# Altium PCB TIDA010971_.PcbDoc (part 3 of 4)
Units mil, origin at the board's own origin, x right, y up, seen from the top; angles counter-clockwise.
Board outline 4500 x 6000 mil, 2 copper layers (F.CU, B.CU), stack 60.617 mil thick; 280 components, 124 nets, 681 pads, 871 vias.
Unrouted connection lines stored in the file: 1.
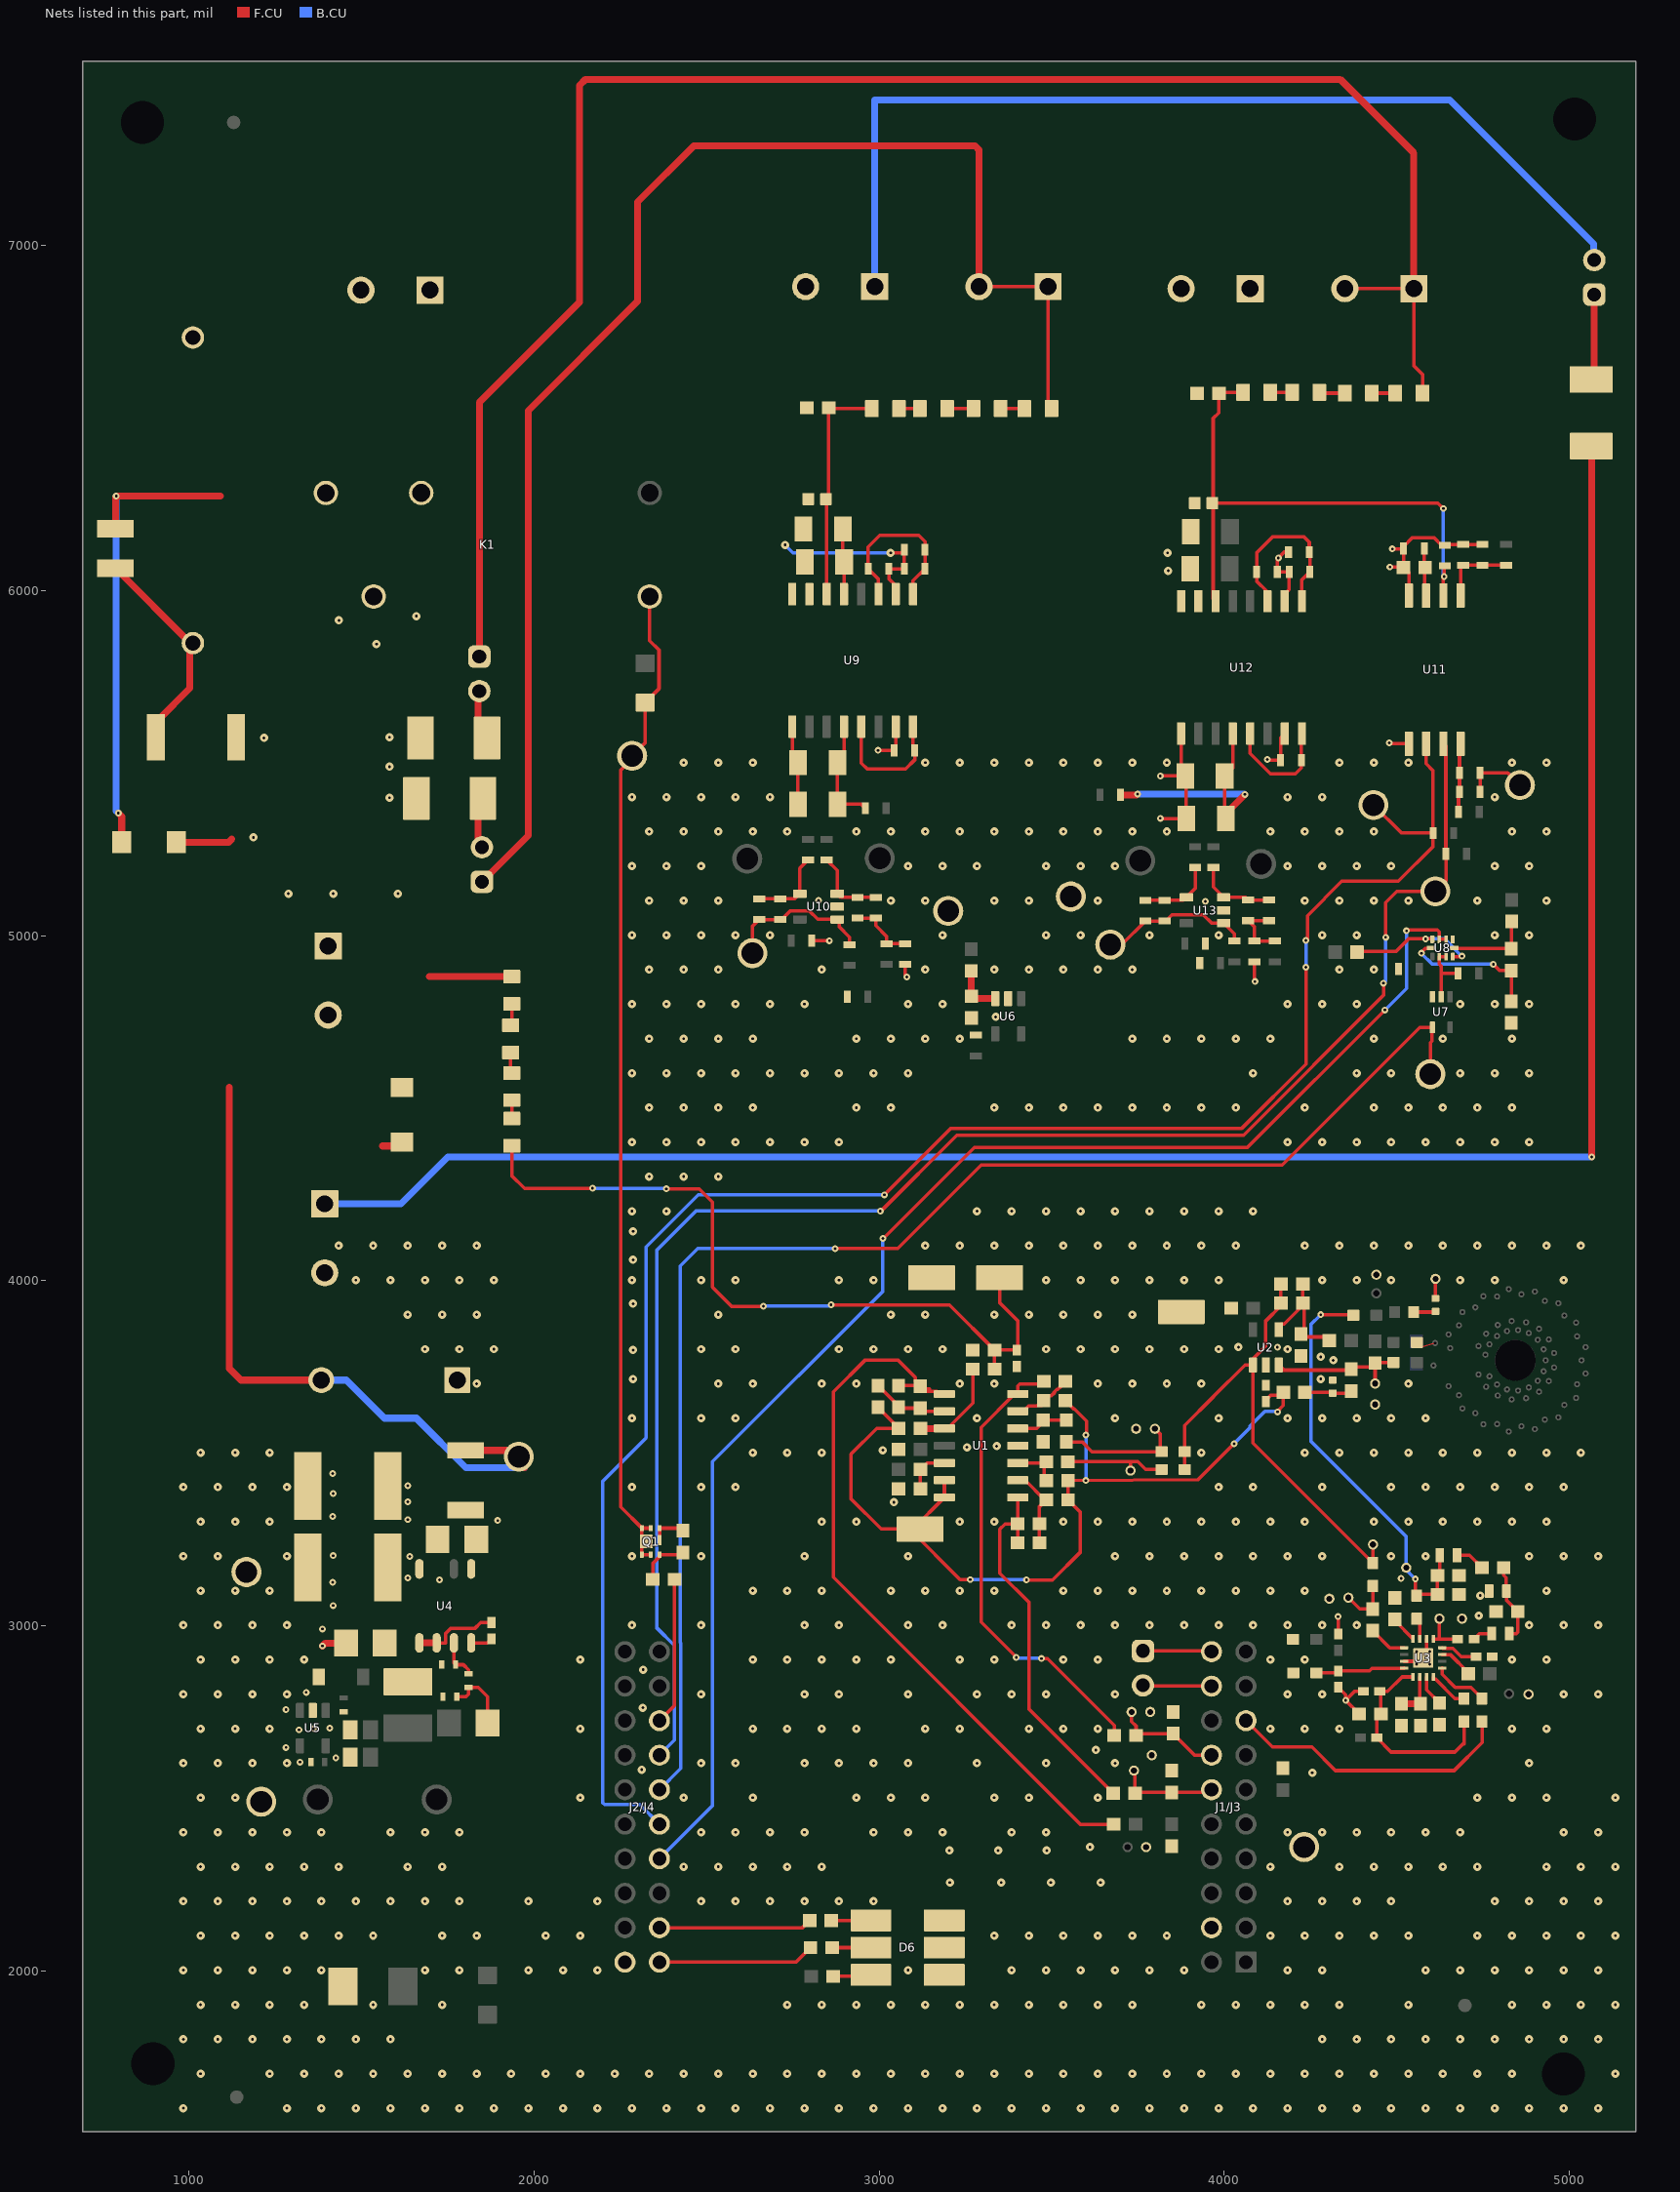
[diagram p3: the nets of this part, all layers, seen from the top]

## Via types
v1: diameter 24, hole 8, F.CU to B.CU, tented both sides, 774 vias
v2: diameter 19.68, hole 7.87, F.CU to B.CU, tented both sides, 97 vias

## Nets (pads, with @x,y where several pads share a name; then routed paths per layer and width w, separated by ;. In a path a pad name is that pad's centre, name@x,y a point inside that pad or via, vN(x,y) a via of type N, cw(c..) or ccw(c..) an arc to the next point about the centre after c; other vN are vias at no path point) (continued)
AGND: AGND2.1 AGND3.1 C2.1 C3.1 C4.1 C5.1 C7.2 C8.1 C9.2 C10.1 C12.2 C13.1 C16.2 C17.2 C18.2 C19.2 C22.2 C23.2 C24.2 C25.2 C26.2 C27.2 C28.2 C31.2 C33.1 C37.2 C39.2 C43.2 C44.2 C45.2 C49.2 C50.2 C54.2 C57.2 C58.2 C64.2 C65.2 C66.1 C67.2 C68.1 C69.1 C72.2 D3.2 D4.2 D6.1 D6.2 D6.3 D7.1 D10.2 F2.2 GND.1 J1/J3.22 J2/J4.20 J9.1 J9.2 L1.1 L4.1 Neutral.1 Q1.4 Q1.7 R15.1 R19.1 R24.2 R25.1 R29.1 R48.2 R65.2 R68.2 R69.1 R76.1 R81.1 R88.1 TP7.1 TP11.1 TP15.1 TP18.1 TP20.1 TP22.1 TP24.1 TP25.1 TP26.1 TP_AGND1.1 TP_AGND2.1 TP_AGND3.1 TP_AGND.1 U1.11 U2.2 U3.10 U3.15 U3.17 U5.2 U6.2 U7.3 U8.1 U9.9 U9.15 U10.2 U11.5 U12.9 U12.15 U13.2 | length 7631.9
  F.CU w10: Q1.7@2363.33,3248.24 Q1.4@2363.33,3282.89 2423.35,3282.89 R76.1@2430.8,3275.44 ; U9.9@2747.75,5605.99 2747.75,5518.41 C43.2@2764.47,5501.68 C44.2@2764.47,5380.95 ; C39.2@2804.43,4985.88 2804.77,4985.54 v2(2855.73,4985.54) ; v2(2996.57,5537.08) C37.2@3042.67,5537.12 3047.75,5542.2 U9.15@3047.75,5605.99 ; R48.2@3075.48,4916.54 3075.48,4887.43 3080.04,4882.87 v2(3080.04,4880.25) ; U1.11@3401.33,3521.86 U1.11@3403.27,3519.93 ; v2(3814.48,5340.25) 3815.23,5339.5 C64.2@3889.75,5339.5 3889.75,5459.99 C65.2@3886.83,5462.92 ; v2(3814.48,5462.92) C65.2@3886.83,5462.92 ; U12.9@3874.85,5585.66 3874.85,5474.9 C65.2@3886.83,5462.92 ; R65.2@4086.74,4928.22 R65.2@4086.74,4924.66 4086.74,4869.07 v2(4088.71,4867.1) ; v2(4124.85,5510.55) 4126.23,5509.18 C58.2@4163.28,5509.18 4163.28,5574.09 U12.15@4174.85,5585.66 ; C66.1@4329.9,2821.73 4351.55,2800.08 v2(4351.55,2783.89) ; C67.2@4329.9,2976.01 v2(4329.92,3026.63) ; C68.1@4390.8,2744.58 4351.55,2783.83 v2(4351.55,2783.89) ; C69.1@4403.37,2809.92 4377.58,2809.92 v2(4351.55,2783.89) ; v2(4477.6,5558.65) 4479.86,5556.39 U11.5@4534.82,5556.39 ; U3.15@4521.12,2896.98 4566.39,2896.98 U3.17@4576.23,2906.83 ; U3.10@4586.08,2961.94 4586.08,2934.38 v2(4594.93,2925.53) ; C49.2@4741.5,5416.66 C50.2@4741.5,5471.77 4821.33,5471.77 TP_AGND3.1@4856.76,5436.34
  F.CU w20: v2(1386.55,2941.54) 1394.89,2949.87 D4.2@1454.51,2949.87 ; 1560.45,4390.45 1605.31,4390.45 D7.1@1616.53,4401.67 ; TP_AGND3.1@4856.76,5436.34 TP_AGND3.1@4871.76,5421.34 ; F2.2@5063.13,6419.21 5065,6417.34 v2(5065,4359)
  B.CU w20: J9.1@1390.97,4223 J9.1@1393,4223 1614,4223 1750,4359 v2(5065,4359)
  other v1: 983.37,1601.73 1283.37,1601.73 1383.37,1601.73 1483.37,1601.73 1583.37,1601.73 1683.37,1601.73 1783.37,1601.73 1883.37,1601.73 1983.37,1601.73 2083.37,1601.73 2183.37,1601.73 2283.37,1601.73 2383.37,1601.73 2483.37,1601.73 2583.37,1601.73 2683.37,1601.73 2783.37,1601.73 2883.37,1601.73 2983.37,1601.73 3083.37,1601.73 3183.37,1601.73 3283.37,1601.73 3383.37,1601.73 3483.37,1601.73 3583.37,1601.73 3683.37,1601.73 3783.37,1601.73 3883.37,1601.73 3983.37,1601.73 4083.37,1601.73 4183.37,1601.73 4283.37,1601.73 4383.37,1601.73 4483.37,1601.73 4583.37,1601.73 4683.37,1601.73 4783.37,1601.73 4883.37,1601.73 4983.37,1601.73 5083.37,1601.73 1033.37,1701.73 1233.37,1701.73 1333.37,1701.73 1433.37,1701.73 1533.37,1701.73 1633.37,1701.73 1733.37,1701.73 1833.37,1701.73 1933.37,1701.73 2033.37,1701.73 2133.37,1701.73 2233.37,1701.73 2333.37,1701.73 2433.37,1701.73 2533.37,1701.73 2633.37,1701.73 2733.37,1701.73 2833.37,1701.73 2933.37,1701.73 3033.37,1701.73 3133.37,1701.73 3233.37,1701.73 3333.37,1701.73 3433.37,1701.73 3533.37,1701.73 3633.37,1701.73 3733.37,1701.73 3833.37,1701.73 3933.37,1701.73 4033.37,1701.73 4133.37,1701.73 4233.37,1701.73 4333.37,1701.73 4433.37,1701.73 4533.37,1701.73 4633.37,1701.73 4733.37,1701.73 4833.37,1701.73 5133.37,1701.73 983.37,1801.73 1083.37,1801.73 1183.37,1801.73 1283.37,1801.73 1383.37,1801.73 1483.37,1801.73 1583.37,1801.73 4283.37,1801.73 4383.37,1801.73 4483.37,1801.73 4583.37,1801.73 4683.37,1801.73 4783.37,1801.73 4883.37,1801.73 4983.37,1801.73 5083.37,1801.73 1033.37,1901.73 1133.37,1901.73 1233.37,1901.73 1333.37,1901.73 1533.37,1901.73 1733.37,1901.73 2733.37,1901.73 2833.37,1901.73 2933.37,1901.73 3033.37,1901.73 3133.37,1901.73 3233.37,1901.73 3333.37,1901.73 3433.37,1901.73 3533.37,1901.73 3633.37,1901.73 3733.37,1901.73 3933.37,1901.73 4033.37,1901.73 4133.37,1901.73 4233.37,1901.73 4333.37,1901.73 4533.37,1901.73 4833.37,1901.73 4933.37,1901.73 5033.37,1901.73 5133.37,1901.73 983.37,2001.73 1083.37,2001.73 1183.37,2001.73 1283.37,2001.73 1383.37,2001.73 1683.37,2001.73 1783.37,2001.73 1983.37,2001.73 2083.37,2001.73 2183.37,2001.73 3083.37,2001.73 3383.37,2001.73 3483.37,2001.73 3583.37,2001.73 3683.37,2001.73 3783.37,2001.73 3883.37,2001.73 4183.37,2001.73 4283.37,2001.73 4583.37,2001.73 4683.37,2001.73 4783.37,2001.73 4883.37,2001.73 4983.37,2001.73 5083.37,2001.73 1033.37,2101.73 1133.37,2101.73 1233.37,2101.73 1333.37,2101.73 1433.37,2101.73 1533.37,2101.73 1733.37,2101.73 1833.37,2101.73 2033.37,2101.73 2133.37,2101.73 3333.37,2101.73 3433.37,2101.73 3533.37,2101.73 3633.37,2101.73 3733.37,2101.73 3833.37,2101.73 4133.37,2101.73 4233.37,2101.73 4333.37,2101.73 4433.37,2101.73 4533.37,2101.73 4733.37,2101.73 4833.37,2101.73 4933.37,2101.73 5033.37,2101.73 5133.37,2101.73 983.37,2201.73 1083.37,2201.73 1183.37,2201.73 1283.37,2201.73 1383.37,2201.73 1483.37,2201.73 1583.37,2201.73 1683.37,2201.73 1783.37,2201.73 1983.37,2201.73 2183.37,2201.73 2483.37,2201.73 2583.37,2201.73 2683.37,2201.73 2783.37,2201.73 2883.37,2201.73 2983.37,2201.73 4183.37,2201.73 4283.37,2201.73 4383.37,2201.73 4483.37,2201.73 4783.37,2201.73 4883.37,2201.73 4983.37,2201.73 5083.37,2201.73 3204.58,2255.72 3353.33,2255.72 3497.35,2255.72 3641.36,2255.72 1033.37,2301.73 1133.37,2301.73 1233.37,2301.73 1333.37,2301.73 1433.37,2301.73 1633.37,2301.73 1733.37,2301.73 2433.37,2301.73 2533.37,2301.73 2633.37,2301.73 2733.37,2301.73 2833.37,2301.73 4133.37,2301.73 4333.37,2301.73 4433.37,2301.73 4533.37,2301.73 4633.37,2301.73 4733.37,2301.73 4933.37,2301.73 5033.37,2301.73 5133.37,2301.73 3203.33,2348.57 3344.57,2348.57 3485.5,2348.57 3610.72,2358.55 983.37,2401.73 1083.37,2401.73 1183.37,2401.73 1283.37,2401.73 1383.37,2401.73 1583.37,2401.73 1683.37,2401.73 1783.37,2401.73 2483.37,2401.73 2583.37,2401.73 2683.37,2401.73 2783.37,2401.73 2983.37,2401.73 3083.37,2401.73 3183.37,2401.73 3383.37,2401.73 3483.37,2401.73 4183.37,2401.73 4283.37,2401.73 4383.37,2401.73 4483.37,2401.73 4583.37,2401.73 4683.37,2401.73 4983.37,2401.73 5083.37,2401.73 1033.37,2501.73 1133.37,2501.73 2133.37,2501.73 2433.37,2501.73 2633.37,2501.73 2933.37,2501.73 3033.37,2501.73 3133.37,2501.73 3333.37,2501.73 3433.37,2501.73 3633.37,2501.73 4733.37,2501.73 4833.37,2501.73 4933.37,2501.73 5133.37,2501.73 4254.74,2574.17 2311.49,2582.75 983.37,2601.73 1083.37,2601.73 1183.37,2601.73 1283.37,2601.73 2483.37,2601.73 2583.37,2601.73 2783.37,2601.73 2883.37,2601.73 2983.37,2601.73 3083.37,2601.73 3283.37,2601.73 3483.37,2601.73 3683.37,2601.73 4883.37,2601.73 3627.65,2640.08 1033.37,2701.73 1133.37,2701.73 1233.37,2701.73 2133.37,2701.73 2633.37,2701.73 2733.37,2701.73 2833.37,2701.73 2933.37,2701.73 3133.37,2701.73 3233.37,2701.73 3433.37,2701.73 3533.37,2701.73 3633.37,2701.73 4133.37,2701.73 4233.37,2701.73 4333.37,2701.73 4833.37,2701.73 4933.37,2701.73 2315.08,2762.66 983.37,2801.73 1083.37,2801.73 1183.37,2801.73 1283.37,2801.73 2483.37,2801.73 2783.37,2801.73 2883.37,2801.73 3083.37,2801.73 3283.37,2801.73 3383.37,2801.73 3483.37,2801.73 3683.37,2801.73 4183.37,2801.73 4283.37,2801.73 4983.37,2801.73 5083.37,2801.73 2316.01,2872.56 1033.37,2901.73 1133.37,2901.73 1233.37,2901.73 1333.37,2901.73 2133.37,2901.73 2633.37,2901.73 2733.37,2901.73 2833.37,2901.73 2933.37,2901.73 3033.37,2901.73 3233.37,2901.73 3333.37,2901.73 3533.37,2901.73 3633.37,2901.73 4133.37,2901.73 4233.37,2901.73 4833.37,2901.73 4933.37,2901.73 983.37,3001.73 1083.37,3001.73 1183.37,3001.73 1283.37,3001.73 2283.37,3001.73 2483.37,3001.73 2783.37,3001.73 2883.37,3001.73 3083.37,3001.73 3183.37,3001.73 3383.37,3001.73 3483.37,3001.73 3583.37,3001.73 3683.37,3001.73 3783.37,3001.73 3883.37,3001.73 3983.37,3001.73 4083.37,3001.73 4183.37,3001.73 4283.37,3001.73 4383.37,3001.73 4883.37,3001.73 4983.37,3001.73 5083.37,3001.73 4737.47,3029.14 4741.78,3087.48 1033.37,3101.73 1133.37,3101.73 1233.37,3101.73 2633.37,3101.73 2733.37,3101.73 2833.37,3101.73 3033.37,3101.73 3133.37,3101.73 3233.37,3101.73 3333.37,3101.73 3533.37,3101.73 3633.37,3101.73 3733.37,3101.73 3833.37,3101.73 3933.37,3101.73 4033.37,3101.73 4133.37,3101.73 4233.37,3101.73 4933.37,3101.73 983.37,3201.73 1083.37,3201.73 1283.37,3201.73 2283.37,3201.73 2483.37,3201.73 2783.37,3201.73 3083.37,3201.73 3683.37,3201.73 3783.37,3201.73 3883.37,3201.73 3983.37,3201.73 4083.37,3201.73 4183.37,3201.73 4283.37,3201.73 4483.37,3201.73 4583.37,3201.73 4883.37,3201.73 4983.37,3201.73 5083.37,3201.73 1033.37,3301.73 1133.37,3301.73 1233.37,3301.73 2833.37,3301.73 2933.37,3301.73 3233.37,3301.73 3333.37,3301.73 3533.37,3301.73 3633.37,3301.73 3733.37,3301.73 3833.37,3301.73 3933.37,3301.73 4033.37,3301.73 4133.37,3301.73 4233.37,3301.73 4433.37,3301.73 4533.37,3301.73 4633.37,3301.73 4733.37,3301.73 4833.37,3301.73 4933.37,3301.73 3042.58,3358.28 983.37,3401.73 1083.37,3401.73 1183.37,3401.73 1283.37,3401.73 2283.37,3401.73 2483.37,3401.73 2583.37,3401.73 3983.37,3401.73 4083.37,3401.73 4283.37,3401.73 4483.37,3401.73 4583.37,3401.73 4683.37,3401.73 4783.37,3401.73 4883.37,3401.73 4983.37,3401.73 1033.37,3501.73 1133.37,3501.73 1233.37,3501.73 2633.37,3501.73 2733.37,3501.73 2833.37,3501.73 3933.37,3501.73 4233.37,3501.73 4333.37,3501.73 4433.37,3501.73 4533.37,3501.73 4633.37,3501.73 4733.37,3501.73 4833.37,3501.73 4933.37,3501.73 5033.37,3501.73 3010.54,3508.83 3254.05,3517.23 3340.05,3520.76 2283.37,3601.73 2483.37,3601.73 2583.37,3601.73 3283.37,3601.73 3683.37,3601.73 3983.37,3601.73 4183.37,3601.73 4283.37,3601.73 4383.37,3601.73 4483.37,3601.73 4583.37,3601.73 1833.37,3701.73 2533.37,3701.73 2633.37,3701.73 2833.37,3701.73 2933.37,3701.73 3233.37,3701.73 3333.37,3701.73 3633.37,3701.73 3733.37,3701.73 3833.37,3701.73 3933.37,3701.73 4533.37,3701.73 2286.57,3715.38 4279.32,3715.19 4315.7,3769.49 4279.32,3779.24 2286.57,3798.98 1683.37,3801.73 1783.37,3801.73 1883.37,3801.73 2483.37,3801.73 2583.37,3801.73 2883.37,3801.73 2983.37,3801.73 3083.37,3801.73 3183.37,3801.73 3483.37,3801.73 3583.37,3801.73 3683.37,3801.73 3783.37,3801.73 3883.37,3801.73 3983.37,3801.73 4183.37,3801.73 4040.81,3807.61 1633.37,3901.73 1733.37,3901.73 1833.37,3901.73 2533.37,3901.73 3033.37,3901.73 3133.37,3901.73 3333.37,3901.73 3433.37,3901.73 3533.37,3901.73 3633.37,3901.73 3733.37,3901.73 2286.57,3933.67 1483.37,4001.73 1583.37,4001.73 1683.37,4001.73 1783.37,4001.73 1883.37,4001.73 2283.37,4001.73 2483.37,4001.73 2583.37,4001.73 2883.37,4001.73 2983.37,4001.73 3483.37,4001.73 3583.37,4001.73 3683.37,4001.73 3783.37,4001.73 3883.37,4001.73 3983.37,4001.73 4283.37,4001.73 4383.37,4001.73 4483.37,4001.73 4683.37,4001.73 4783.37,4001.73 4983.37,4001.73 2286.57,4060.68 1433.37,4101.73 1533.37,4101.73 1633.37,4101.73 1733.37,4101.73 1833.37,4101.73 3133.37,4101.73 3233.37,4101.73 3333.37,4101.73 3433.37,4101.73 3533.37,4101.73 3633.37,4101.73 3733.37,4101.73 3833.37,4101.73 3933.37,4101.73 4033.37,4101.73 4233.37,4101.73 4333.37,4101.73 4433.37,4101.73 4533.37,4101.73 4633.37,4101.73 4733.37,4101.73 4833.37,4101.73 4933.37,4101.73 5033.37,4101.73 2286.57,4142.96 2283.37,4201.73 2383.37,4201.73 3283.37,4201.73 3383.37,4201.73 3483.37,4201.73 3583.37,4201.73 3683.37,4201.73 3783.37,4201.73 3883.37,4201.73 3983.37,4201.73 4083.37,4201.73 2333.37,4301.73 2433.37,4301.73 2533.37,4301.73 2283.37,4401.73 2383.37,4401.73 2483.37,4401.73 2583.37,4401.73 2683.37,4401.73 2783.37,4401.73 2883.37,4401.73 4183.37,4401.73 4283.37,4401.73 4383.37,4401.73 4483.37,4401.73 4583.37,4401.73 4683.37,4401.73 4783.37,4401.73 4883.37,4401.73 2333.37,4501.73 2433.37,4501.73 2533.37,4501.73 2633.37,4501.73 2933.37,4501.73 3033.37,4501.73 3333.37,4501.73 3433.37,4501.73 3533.37,4501.73 3633.37,4501.73 3733.37,4501.73 3833.37,4501.73 3933.37,4501.73 4033.37,4501.73 4233.37,4501.73 4433.37,4501.73 4533.37,4501.73 4633.37,4501.73 4733.37,4501.73 4833.37,4501.73 2283.37,4601.73 2383.37,4601.73 2483.37,4601.73 2583.37,4601.73 2683.37,4601.73 2783.37,4601.73 2883.37,4601.73 2983.37,4601.73 3083.37,4601.73 4083.37,4601.73 4383.37,4601.73 4483.37,4601.73 4683.37,4601.73 4783.37,4601.73 4883.37,4601.73 2333.37,4701.73 2433.37,4701.73 2533.37,4701.73 2633.37,4701.73 2933.37,4701.73 3033.37,4701.73 3133.37,4701.73 3233.37,4701.73 3733.37,4701.73 3833.37,4701.73 3933.37,4701.73 4033.37,4701.73 4133.37,4701.73 4433.37,4701.73 4633.37,4701.73 4833.37,4701.73 3337.24,4764.51 2283.37,4801.73 2383.37,4801.73 2483.37,4801.73 2583.37,4801.73 2683.37,4801.73 2783.37,4801.73 3083.37,4801.73 3183.37,4801.73 4183.37,4801.73 4283.37,4801.73 4383.37,4801.73 4683.37,4801.73 4783.37,4801.73 4883.37,4801.73 2333.37,4901.73 2433.37,4901.73 2533.37,4901.73 2833.37,4901.73 3133.37,4901.73 3333.37,4901.73 3433.37,4901.73 3533.37,4901.73 3633.37,4901.73 3733.37,4901.73 4333.37,4901.73 4433.37,4901.73 2283.37,5001.73 2383.37,5001.73 2483.37,5001.73 2583.37,5001.73 2683.37,5001.73 3183.37,5001.73 3483.37,5001.73 3583.37,5001.73 3783.37,5001.73 3983.37,5001.73 4283.37,5001.73 4383.37,5001.73 4783.37,5001.73 4883.37,5001.73 2333.37,5101.73 2433.37,5101.73 2533.37,5101.73 3033.37,5101.73 3133.37,5101.73 3333.37,5101.73 3433.37,5101.73 3633.37,5101.73 4233.37,5101.73 4333.37,5101.73 4433.37,5101.73 4533.37,5101.73 4733.37,5101.73 4933.37,5101.73 2283.37,5201.73 2383.37,5201.73 2483.37,5201.73 3083.37,5201.73 3183.37,5201.73 3283.37,5201.73 3483.37,5201.73 3583.37,5201.73 3683.37,5201.73 4183.37,5201.73 4283.37,5201.73 4383.37,5201.73 4483.37,5201.73 4783.37,5201.73 4883.37,5201.73 2333.37,5301.73 2433.37,5301.73 2533.37,5301.73 2633.37,5301.73 2733.37,5301.73 2933.37,5301.73 3033.37,5301.73 3133.37,5301.73 3233.37,5301.73 3333.37,5301.73 3433.37,5301.73 3533.37,5301.73 3633.37,5301.73 3733.37,5301.73 3833.37,5301.73 4133.37,5301.73 4233.37,5301.73 4333.37,5301.73 4433.37,5301.73 4833.37,5301.73 4933.37,5301.73 2283.37,5401.73 2383.37,5401.73 2483.37,5401.73 2583.37,5401.73 2683.37,5401.73 4183.37,5401.73 4283.37,5401.73 4783.37,5401.73 2433.37,5501.73 2533.37,5501.73 2633.37,5501.73 3133.37,5501.73 3233.37,5501.73 3333.37,5501.73 3433.37,5501.73 3533.37,5501.73 3633.37,5501.73 3733.37,5501.73 3833.37,5501.73 4333.37,5501.73 4433.37,5501.73 4533.37,5501.73 4833.37,5501.73 4933.37,5501.73
  other v2: 1321.1,2604.93 1425.27,2616.74 1280.85,2647.25 1318.59,2698.37 1360.47,2701.39 1407.72,2703.35 1280.85,2757.34 1339.08,2806.96 4557.53,2888.13 4594.94,2888.12 4557.53,2925.53 1386.55,2990.95 1417.4,3058.64 1415.78,3126.3 4512.52,3137.16 1417.4,3203.16 1415.78,3317.06 1417.4,3382.95 1415.78,3441.54 4153.63,3807.07 3945.24,5099.54 2824.39,5102.54
BP_in: C12.1 L1.2 L3.2 R21.2 R70.2 TP1.1 | length 1231.4
  F.CU w10: v2(4279.32,3901.67) 4280.23,3900.76 4372.83,3900.76 R70.2@4373.73,3899.86 ; R21.2@4553.66,3089.55 v2(4553.66,3135.31) ; R21.2@4557.53,3087.48 4560.86,3090.8 L1.2@4617.54,3090.8 C12.1@4617.54,3145.8 4624.25,3152.51 L3.2@4624.25,3204.65
  B.CU w10: v2(4279.32,3901.67) 4250.49,3872.83 4250.49,3535.64 4527.22,3258.91 TP1.1@4527.22,3168.28 TP1.1@4523.95,3171.55 ; TP1.1@4520.69,3169.53 4520.69,3168.28 v2(4553.66,3135.31)
COMP_arc_extinguished: J2/J4.35 TP_AE.1 U7.4 | length 4146.7
  F.CU w10: v2(2872.08,4093.28) 2872.18,4093.38 3053.76,4093.38 3295.38,4335 4167.21,4335 4566.65,4734.43 U7.4@4603.23,4734.43 ; TP_AE.1@4597,4599 4597,4690.69 4602.31,4696 U7.4@4602.31,4733.51
  B.CU w10: J2/J4.35@2363,2525 2424.26,2586.26 2424.26,2950.37 2423.35,2951.29 2423.35,4042.97 2473.66,4093.28 v2(2872.08,4093.28)
COMP_VGap: J2/J4.36 R52.1 TP_Cgap.1 U11.6 | length 5379.8
  F.CU w10: v2(3015,4249) 3208,4442 4051,4442 4236.58,4627.58 v2(4236.58,4908.22) ; v2(4236.58,4986.53) 4240.95,4990.89 4240.95,5058 4340.57,5157.62 4504.36,5157.62 4605.13,5258.4 4604.82,5258.71 R52.1@4604.82,5297.51 ; TP_Cgap.1@4432.27,5378.87 4513.63,5297.51 R52.1@4604.82,5297.51 ; U11.6@4584.82,5556.39 4580.38,5551.95 4584.82,5547.51 4584.82,5498.35 4604.82,5478.35 R52.1@4604.82,5297.51
  B.CU w10: J2/J4.36@2363,2425 2306.39,2481.61 2204,2481.61 2199,2486.61 2199,3419.02 2324.61,3544.64 2324.61,4097.61 2476,4249 v2(3015,4249) ; v2(4236.58,4908.22) v2(4236.58,4986.53)
COMP_VGap_LATCH: J2/J4.34 R51.1 TP_Latch.1 U11.7 | length 4787.9
  F.CU w10: v2(3003,4202) 3004.8,4202 3224.8,4422 4056.28,4422 4461.2,4826.92 v2(4461.2,4862.49) ; v2(4467.54,4995.34) 4467.54,5095.97 4500.25,5128.69 TP_Latch.1@4611.79,5128.69 4642.13,5159.03 4642.13,5248.83 4641.95,5249.01 4641.95,5549.09 4642.13,5549.09 U11.7@4634.82,5556.39
  B.CU w10: J2/J4.34@2363,2625 2406.39,2668.39 2406.39,2942.97 2354.89,2994.47 2354.89,4088.23 2468.65,4202 v2(3003,4202) ; v2(4461.2,4862.49) 4467.54,4868.83 v2(4467.54,4995.34)
COMP_VGap_VString: R89.1 U7.2 U8.7 U8.8 | length 187.1
  F.CU w10: U7.2@4628.82,4823.02 4628.82,4891.2 ; U8.8@4642.31,4939.25 U8.7@4622.62,4939.25 4622.62,4917.76 4628.82,4911.57 4628.82,4891.2 ; R89.1@4677.47,4891.2 4628.82,4891.2
Current_BP: C7.1 J1/J3.26 R22.2 TP12.1 | length 293.3
  F.CU w10: TP12.1@3738.28,2580.3 3741,2577.59 R22.2@3741,2514.36 3743.95,2517.31 C7.1@3847.78,2517.31 3955.09,2517.31 J1/J3.26@3962.78,2525
Current_LP: C19.1 J1/J3.27 R18.2 TP17.1 | length 319.9
  F.CU w10: TP17.1@3731.28,2750.23 3731.28,2722.66 3744.28,2709.67 R18.2@3744.28,2682.12 3749.39,2687.24 C19.1@3851.56,2687.24 3913.8,2625 J1/J3.27@3962.78,2625
ex_latch: J2/J4.37 U8.2 U8.3 | length 4191.3
  F.CU w10: v2(3010.54,4123) 3012.95,4123 3275.95,4386 4066.82,4386 v2(4465.54,4784.73) ; v2(4528,5014) v2(4528,5014) 4527.96,5016.69 4616.77,5016.69 4622.62,5010.83 U8.3@4622.62,4989.44 U8.2@4642.31,4989.44
  B.CU w10: J2/J4.37@2363,2325 2516.5,2478.5 2516.5,3475.54 3010.54,3969.58 v2(3010.54,4123) ; v2(4465.54,4784.73) 4528,4847.18 v2(4528,5014)
FreqDetect: J1/J3.8 R75.1 | length 838.8
  F.CU w10: J1/J3.8@4062.78,2725 4139.28,2648.5 4253.78,2648.5 4321.98,2580.3 4665.97,2580.3 4746.85,2661.18 R75.1@4746.85,2722.49
GND_iso_AMC23C12: C47.2 C48.2 C52.2 C53.2 C55.2 C56.2 C59.1 C61.1 C62.2 C63.2 J5.1 J5.2 R54.1 R66.1 U11.4 U12.2 U12.7 U12.8 | length 678.7
  F.CU w10: R66.1@3916.52,6567.13 R66.1@3921.06,6571.67 ; U12.2@4174.85,5969.52 4174.85,5990.19 4181.66,5997 4181.87,5997 4187.73,6002.85 C56.2@4187.73,6054.71 C59.1@4153.62,6054.71 4153.62,6091.98 v2(4156.46,6094.82) 4173.32,6111.68 C55.2@4186.14,6111.68 ; v2(4479.86,6068.53) R54.1@4519.23,6068.53 ; v2(4486.96,6120.92) 4517.85,6120.92 C53.2@4519.23,6122.3 ; U11.4@4534.82,5985.53 4534.82,6052.94 R54.1@4519.23,6068.53 ; C48.2@4748.16,6133.66 C47.2@4691.81,6133.66 4630.31,6133.66 4628.82,6132.18 4608.33,6152.67 4543.7,6152.67 4519.23,6128.21 C53.2@4519.23,6122.3 ; R54.1@4519.23,6068.53 C53.2@4519.23,6122.3
  other v1: 3837.19,6057.72 3835.37,6109.65
hv2: K1.2
HVIN: C22.1 C23.1 D2.1 U4.5 U4.8
  other v2: 1725.81,3133.36 1634.09,3138.39 1639,3200.87 1634.09,3307.68 1634.09,3358.93 1634.09,3405.6
intOut: C11.1 R6.2 R67.1 R86.1 R87.1 TP9.1 U2.1 | length 1438.1
  F.CU w10: R86.1@3885.2,3452.98 R87.1@3885.2,3504.56 3885.2,3580.56 3967.83,3663.19 3967.83,3663.5 4060.22,3755.89 U2.1@4082.86,3755.89 ; U2.1@4076.05,3739.23 4080,3743.18 U2.1@4082.86,3743.18 ; R6.2@4163.42,3982.09 4163.42,3926.86 4120.4,3883.84 4120.26,3883.84 4120.26,3811 4082.86,3773.6 U2.1@4082.86,3755.89 ; TP9.1@4430.86,3235.66 4430.86,3182.42 R67.1@4430.29,3181.85 4082.86,3529.28 U2.1@4082.86,3743.18 ; U2.1@4082.86,3743.18 U2.1@4082.86,3755.89
LNA_en: C66.2 R68.1 U3.16 | length 260.1
  F.CU w10: R68.1@4266.74,2863.52 4324.44,2863.52 C66.2@4329.9,2868.98 4420.33,2868.98 4428.2,2876.85 4520.67,2876.85 U3.16@4521.12,2877.3
LNA_O: R21.1 U3.11 | length 69
  F.CU w10: R21.1@4564.3,3020.55 R21.1@4557.53,3020.55 4566.39,3011.69 U3.11@4566.39,2961.94
Log+: C70.1 TP5.1 U3.9 | length 130
  F.CU w10: U3.9@4605.76,2961.94 4622.53,2961.94 ; TP5.1@4623.42,3020.55 4623.42,2962.83 4622.53,2961.94 ; C70.1@4676.38,2961 4675.43,2961.94 4622.53,2961.94
Log-: C16.1 U3.8 | length 108.9
  F.CU w10: U3.8@4631.35,2936.35 4633.16,2934.54 4662.2,2934.54 4686.74,2910 C16.1@4729.38,2910
midSupply: 1.1 C72.1 R4.2 R5.1 R7.1 R9.2 R23.1 R83.2 U1.6 U1.7 | length 2666.6
  F.CU w10: R23.1@2996.31,3633.13 3055.97,3573.47 R83.2@3055.97,3571.86 2992.51,3571.86 2918.33,3497.68 2918.33,3367.56 3005.46,3280.43 1.1@3087.5,3280.43 ; U1.6@3188.74,3421.86 U1.7@3188.74,3371.86 3097.31,3280.43 1.1@3087.5,3280.43 ; v2(3263.88,3133.77) 3234.17,3133.77 1.1@3087.5,3280.43 ; v2(3426.85,3132.82) 3502.29,3132.82 3582.96,3213.49 3582.96,3328.96 R5.1@3547,3364.93 R9.2@3547,3420.93 3923.95,3423.21 v2(4028.04,3527.3) ; R7.1@3539.33,3652.54 3540.31,3652.54 3554.01,3638.84 3554.01,3637.85 3563.27,3628.59 3565.87,3628.59 3600.79,3593.67 3600.79,3555.01 v2(3598.93,3553.16) ; C72.1@4121,3654.66 4134.43,3668.09 4162.37,3668.09 R4.2@4170.99,3676.72 4170.99,3638.19 4154.23,3621.42 v2(4154.23,3619.82)
  B.CU w10: v2(3263.88,3133.77) 3425.9,3133.77 v2(3426.85,3132.82) ; v2(3598.93,3420.93) v2(3598.93,3553.16) ; v2(4028.04,3527.3) 4073.79,3573.05 4073.79,3577.42 4117.68,3621.31 4152.74,3621.31 v2(4154.23,3619.82)
NetC1_1: C1.1 U3.13 | length 111.4
  F.CU w10: C1.1@4430.17,2985.75 4479.56,2936.35 U3.13@4521.12,2936.35
NetC1_2: C1.2 R67.2 TP2.1 | length 150.4
  F.CU w10: TP2.1@4359.52,3081.3 4392.09,3048.74 C1.2@4430.17,3048.74 4430.17,3114.8 R67.2@4430.29,3114.92
NetC3_2: C3.2 R2.2 R4.1 | length 146.9
  F.CU w10: R4.1@4240.41,3670.3 R4.1@4233.99,3676.72 4311.28,3676.72 C3.2@4314,3674 4361.49,3674 R2.2@4368,3680.5
NetC5_2: C5.2 C11.2 R3.2 R6.1 U2.4 | length 331.7
  F.CU w10: U2.4@4157.66,3858.25 4157.66,3868.09 4164.48,3874.9 4173.47,3874.9 4225.42,3926.86 C11.2@4226.41,3926.86 ; R6.1@4229.36,3985.05 4226.41,3982.09 C11.2@4226.41,3926.86 ; R3.2@4304.32,3826.3 4293.5,3837.12 4231.19,3837.12 4231.19,3922.07 C11.2@4226.41,3926.86
NetC6_1: C6.1 R9.1 U1.10 | length 137.3
  F.CU w10: U1.10@3401.33,3471.86 3472.94,3471.86 3478.01,3476.93 3478.01,3426.93 R9.1@3484.01,3420.93
NetC6_2: C6.2 R86.2 TP10.1 | length 306.6
  F.CU w10: C6.2@3546.82,3475.54 3728.2,3475.54 ; TP10.1@3728.2,3449.73 3728.2,3475.54 ; R86.2@3818.27,3452.98 3818.24,3452.94 3771.89,3452.94 3749.29,3475.54 3728.2,3475.54
NetC8_2: C8.2 U3.12 | length 78.2
  F.CU w10: C8.2@4493.95,3018.31 4493.95,3014.7 U3.12@4546.71,2961.94
NetC10_2: C10.2 R15.2 U3.2 | length 134
  F.CU w10: U3.2@4566.39,2851.71 4566.39,2775.79 R15.2@4568.58,2773.6
  F.CU w20: C10.2@4513.58,2773.6 R15.2@4568.58,2773.6
NetC13_2: C13.2 R8.2 U1.12 | length 156.4
  F.CU w10: U1.12@3401.33,3571.86 3456.14,3571.86 3480.32,3596.03 R8.2@3541.83,3596.03 ; C13.2@3473.43,3596.87 C13.2@3479.36,3596.87
NetC14_1: C14.1 C18.1 L4.2 L5.1 | length 230.5
  F.CU w10: C14.1@4809.5,3168.28 4809.5,3146.45 4816.21,3139.74 4816.21,3102.1 L4.2@4817.81,3100.49 4817.81,3073.63 C18.1@4850.44,3041 4850.44,2981.65 4846.18,2977.39 L5.1@4825.3,2977.39
NetC14_2: C14.2 L3.1 | length 106.3
  F.CU w10: L3.1@4674.64,3204.65 4710.14,3204.65 C14.2@4746.5,3168.28 C14.2@4732.8,3154.58
NetC15_1: C15.1 R17.2 R22.1 U1.8 | length 1091.6
  F.CU w10: R17.2@3401.21,3240.76 C15.1@3401.21,3295.43 ; U1.8@3401.33,3371.86 3401.21,3371.74 C15.1@3401.21,3295.43 ; R22.1@3678,2514.36 3434.53,2757.83 3434.53,3066.88 3349,3152.4 3349,3279.95 3364.47,3295.43 C15.1@3401.21,3295.43
NetC15_2: C15.2 R5.2 R17.1 U1.9 | length 238.6
  F.CU w10: U1.9@3401.33,3421.86 3422.69,3421.86 3479.63,3364.93 R5.2@3484.01,3364.93 3464.2,3345.12 C15.2@3464.2,3295.43 R17.1@3464.2,3240.76
NetC20_1: C20.1 D1.1 R26.2 | length 199
  F.CU w10: C20.1@1775.43,2795.15 1802.41,2795.15 1809.29,2802.03 R26.2@1809.29,2821.15 1838.29,2821.15 1865.11,2794.33 D1.1@1865.11,2718.12
NetC20_2: C20.2 C21.2 D4.1 L2.1 R28.1 U4.1 U4.2 | length 248.7
  F.CU w10: U4.2@1717.36,2950.4 1742.68,2950.4 1742.68,2977.36 1757.14,2991.82 1827.59,2991.82 1845.34,3009.57 C21.2@1875.74,3009.57
  F.CU w20: U4.1@1667.36,2950.4 U4.2@1717.36,2950.4
NetC21_1: C21.1 U4.4 | length 63.3
  F.CU w10: U4.4@1817.36,2950.4 1863.82,2950.4 C21.1@1875.74,2962.32
NetC24_1: C24.1 C29.2 R14.2 R19.2 TP_VIN.1 | length 2195.2
  F.CU w10: R14.2@1935.04,4391.13 1935.04,4304.64 1972,4267.68 2168.68,4267.68 v2(2169,4268) ; v2(2382.61,4266.28) 2478.53,4266.28 2516.5,4228.31 2516.5,3981.41 2571.98,3925.93 2664.34,3925.93 v2(2664.64,3926.23) ; v2(2860.16,3930.14) 3203.13,3930.14 R19.2@3334.29,3798.98 ; C29.2@3334.29,3743.93 R19.2@3334.29,3798.98 ; TP_VIN.1@3349,4008.52 3349,3936.05 3401.21,3883.84 3401.21,3801.49 C24.1@3398.7,3798.98 R19.2@3334.29,3798.98
  B.CU w10: v2(2169,4268) 2169.86,4267.14 2381.75,4267.14 v2(2382.61,4266.28) ; v2(2664.64,3926.23) 2856.25,3926.23 v2(2860.16,3930.14)
NetC29_1: C29.1 R83.1 U1.3 | length 281.5
  F.CU w10: U1.3@3188.74,3571.86 3198.09,3571.86 3271.3,3645.07 C29.1@3271.3,3743.93
  F.CU w20: R83.1@3118.96,3571.86 U1.3@3188.74,3571.86
NetC30_1: C30.1 R20.1 R31.2 U1.1 | length 2142.8
  F.CU w10: R31.2@3055.84,3696.12 3116.16,3696.12 C30.1@3118.56,3693.73 3104.88,3707.41 3104.88,3719.64 3054.08,3770.44 2959.64,3770.44 2866.82,3677.62 2866.82,3140.64 3582.96,2424.5 R20.1@3679.37,2424.5 ; C30.1@3116.02,3695.98 C30.1@3125.41,3686.59 ; 3145.92,3686.59 C30.1@3125.41,3686.59 ; U1.1@3188.74,3671.86 3174.14,3671.86 3167.33,3678.67 3167.33,3679.74 3132.26,3679.74 C30.1@3125.41,3686.59
NetC30_2: C30.2 R23.2 R31.1 U1.2 | length 225.2
  F.CU w10: R23.2@2996.31,3696.12 3055.84,3636.6 R31.1@3055.84,3633.13 3058.23,3630.74 C30.2@3118.56,3630.74 3127.43,3621.86 U1.2@3188.74,3621.86
NetC32_1: C32.1 TP6.1 | length 56.6
  F.CU w10: C32.1@4612,3948.81 TP6.1@4612,4005.45
NetC32_2: C32.2 R85.1 | length 53
  F.CU w10: R85.1@4548.25,3909.14 C32.2@4601.22,3909.14
NetC34_1: C34.1 C35.1 C38.2 U9.1 U9.3 | length 502.1
  F.CU w10: U9.3@2997.75,5989.84 2997.75,6033.43 C34.1@2967.75,6063.43 2967.75,6126.88 3001.1,6160.23 3114.07,6160.23 3132.67,6141.62 C38.2@3132.67,6118.55 C35.1@3132.67,6063.43 3097.75,6028.51 U9.1@3097.75,5989.84
NetC34_2: C34.2 C35.2 C38.1 C40.1 C41.2 C42.2 J3.1 J3.2 J13.2 R42.1 U9.2 U9.7 U9.8 | length 3386.7
  F.CU w10: v1(3033.06,6109.65) 3063.77,6109.65 C38.1@3072.67,6118.55 C35.2@3072.67,6063.43 C34.2@3027.75,6063.43 3027.75,6035.05 3047.75,6015.05 U9.2@3047.75,5989.84
  B.CU w10: v1(2727.07,6132.52) 2749.95,6109.65 v1(3033.06,6109.65)
  B.CU w20: J3.1@2986.74,6881.14 2986.74,7421.44 2986.14,7422.04 4653.76,7422.04 5070.77,7005.03 5070.77,6959.41 J13.2@5072.14,6958.04
NetC36_1: C36.1 R36.2 R44.1 TP_VSTRING.1 U10.1 | length 440.2
  F.CU w10: TP_VSTRING.1@2632.4,4949.34 2632.4,5027.34 R36.2@2652.09,5047.03 C36.1@2713.1,5047.03 2717.3,5047.03 2741.89,5071.62 2797.33,5071.62 2821.56,5047.38 2877.8,5047.38 2883.89,5041.29 2883.89,5025.98 2914.22,4995.65 R44.1@2914.22,4974.06
NetC36_2: C36.2 R36.1 R43.2 U10.4 | length 231.7
  F.CU w10: R36.1@2652.09,5107.03 C36.2@2713.1,5107.03 2755.28,5107.03 U10.4@2769.98,5121.73 2769.98,5195.5 R43.2@2794,5219.52
NetC37_1: C37.1 U9.13 U9.16 | length 377.2
  F.CU w10: U9.13@2947.75,5605.99 2947.75,5502.14 2948.21,5501.68 2948.21,5500.06 2965.27,5483 3076.28,5483 3102.67,5509.39 C37.1@3102.67,5537.12 3097.75,5542.04 U9.16@3097.75,5605.99
NetC40_2: C40.2 R39.2 R42.2 U9.6 | length 670.4
  F.CU w10: U9.6@2847.75,5989.84 2847.75,6263.32 C40.2@2845.64,6265.44 2853.51,6273.31 R42.2@2853.51,6530.2 2855.84,6527.87 R39.2@2978.47,6527.87
NetC41_1: C41.1 C42.1 U9.5 | length 190.8
  F.CU w10: C41.1@2894.39,6178.78 2894.39,6087.06 C42.1@2898.33,6083.12 2897.75,6082.54 U9.5@2897.75,5989.84
NetC43_1: C43.1 C44.1 R41.1 U9.12 | length 318.8
  F.CU w10: U9.12@2897.75,5605.99 2897.75,5520.79 C43.1@2878.65,5501.68 C44.1@2878.65,5380.95 2948.21,5380.95 R41.1@2959.75,5369.41
NetC46_1: C46.1 R45.2 R46.2 U10.3 | length 226.5
  F.CU w10: R45.2@2847.75,5219.52 2878.25,5189.01 U10.3@2878.25,5121.73 2889.14,5110.85 C46.1@2937.27,5110.85 R46.2@2989.78,5110.85
NetC46_2: C46.2 R46.1 R47.2 R48.1 | length 194.2
  F.CU w10: C46.2@2937.27,5050.85 R46.1@2989.78,5050.85 2989.78,5029.05 3020.97,4997.86 R47.2@3020.97,4976.54 R48.1@3075.48,4976.54
NetC47_1: C47.1 C48.1 R49.2 U11.1 | length 215.8
  F.CU w10: U11.1@4684.82,5985.53 4684.82,6066.67 C47.1@4691.81,6073.66 C48.1@4748.16,6073.66 R49.2@4816.53,6073.66
NetC49_1: C49.1 C50.1 R50.1 U11.8 | length 199.7
  F.CU w10: R50.1@4678.69,5359.18 4678.69,5413.85 C49.1@4681.5,5416.66 C50.1@4681.5,5471.77 4681.5,5553.07 U11.8@4684.82,5556.39
NetC51_1: C51.1 R53.2 R56.1 TP_Vgap.1 U13.1 | length 441.6
  F.CU w10: TP_Vgap.1@3669.63,4973.95 3702.54,4973.95 R53.2@3771.18,5042.59 C51.1@3826.89,5042.59 3834.39,5042.59 3839.39,5047.59 3839.39,5051.77 3848.52,5060.9 3913.62,5060.9 3914.09,5060.43 3939.07,5060.43 3963.28,5036.22 U13.1@3998.05,5036.22 4029.19,5005.08 R56.1@4029.19,4984.66
NetC51_2: C51.2 R53.1 R55.2 U13.4 | length 219.3
  F.CU w10: R53.1@3771.18,5102.59 C51.2@3826.89,5102.59 3881.35,5102.59 U13.4@3889.78,5111.02 3915.44,5136.68 R55.2@3915.44,5197.62
NetC52_1: C52.1 C61.2 R60.2 R66.2 U11.2 U12.6 | length 1644.6
  F.CU w10: C61.2@3965.23,6253.81 C61.2@3967.7,6253.81 ; U12.6@3974.85,5969.52 3967.7,5976.67 C61.2@3967.7,6253.81 ; R60.2@4054.25,6574.86 3987.24,6574.86 R66.2@3984.05,6571.67 3984.05,6515.67 3967.7,6499.31 C61.2@3967.7,6253.81 ; U11.2@4634.82,5985.53 v2@4634.82,6041.17 ; v2(4634.82,6238.1) 4619.11,6253.81 4552.46,6253.81 C61.2@3967.7,6253.81 ; v2(4637,6041.17) 4637,6070 C52.1@4639,6072
  B.CU w10: v2(4634.82,6238.1) 4634.82,6043.35 v2(4637,6041.17)
NetC53_1: C53.1 R54.2 U11.3 | length 139.1
  F.CU w10: C53.1@4579.23,6122.3 4579.23,6068.53 4580.38,6067.38 4580.38,5989.97 U11.3@4584.82,5985.53
NetC55_1: C55.1 C56.1 C59.2 U12.1 U12.3 | length 511.6
  F.CU w10: U12.3@4124.85,5969.52 4124.85,5996.37 4093.62,6027.6 C59.2@4093.62,6054.71 4093.62,6109.2 4140.11,6155.69 4230.55,6155.69 4246.14,6140.1 C55.1@4246.14,6111.68 4247.73,6110.09 C56.1@4247.73,6054.71 4224.85,6031.83 U12.1@4224.85,5969.52
NetC58_1: C58.1 U12.13 U12.16 | length 337
  F.CU w10: U12.13@4074.85,5585.66 4074.85,5528.43 4133.91,5469.36 4206.06,5469.36 4223.28,5486.58 C58.1@4223.28,5509.18 4223.28,5584.09 U12.16@4224.85,5585.66
NetC60_1: C60.1 R59.2 R61.2 U13.3 | length 234.1
  F.CU w10: R59.2@3967.92,5197.62 3967.92,5141.14 U13.3@3998.05,5111.02 4061.62,5111.02 C60.1@4069.03,5103.62 R61.2@4130.03,5103.62
NetC60_2: C60.2 R61.1 R64.2 R65.1 | length 187.3
  F.CU w10: R61.1@4130.03,5043.62 C60.2@4069.03,5043.62 4086.74,5025.9 R65.1@4086.74,4984.66 R64.2@4146.74,4984.66
NetC64_1: C64.1 C65.1 R63.1 U12.12 | length 712
  F.CU w10: C64.1@4003.92,5339.5 4001,5342.42 C65.1@4001,5462.92 4024.85,5486.76 U12.12@4024.85,5585.66
  F.CU w20: R63.1@3699.63,5407.8 3745.25,5407.8 v2(3748.17,5410.72) ; C64.1@4003.92,5339.5 4003.92,5353.78 v2(4059.62,5409.47)
  B.CU w20: v2(3748.17,5410.72) 4058.37,5410.72 v2(4059.62,5409.47)
NetC68_2: C68.2 C69.2 R73.2 R74.1 U3.1 | length 599
  F.CU w10: U3.1@4546.71,2851.71 4546.61,2851.81 4515.21,2851.81 4473.32,2809.92 C69.2@4450.61,2809.92 4453.79,2806.74 C68.2@4453.79,2744.58 4441.98,2732.77 R74.1@4441.98,2675.31 4483.27,2634.02 4668.23,2634.02 4690.96,2656.76 4694.65,2656.76 R73.2@4694.65,2722.31
NetC70_2: C70.2 L5.2 | length 58.1
  F.CU w10: C70.2@4723.62,2961 4740.01,2977.39 L5.2@4774.9,2977.39
NetC71_1: C71.1 R71.2 R72.1 | length 572.7
  F.CU w20: R72.1@786.49,6064.91 1003.4,5848 C71.1@1011,5848 ; R71.2@911,5626 1002,5717 1002,5821.59 C71.1@1019.71,5839.29
NetCTR_1: CTR.1 D5.2 K1.5 Q1.1 Q1.2 Q1.5 Q1.6 Q1.8 | length 2921.4
  F.CU w10: K1.5@2334.56,5983.28 2334.56,5855.27 2361.73,5828.09 2361.73,5715.89 D5.2@2321.3,5675.45 2321.3,5558.73 CTR.1@2283.9,5521.33 2283.9,5512.68 2251,5479.78 2251,3344.04 Q1.6@2312.15,3282.89 ; Q1.2@2337.74,3206.12 Q1.1@2312.15,3206.12 2312.15,3231.71 Q1.8@2324.95,3244.5 2312.15,3257.3 Q1.6@2312.15,3282.89 ; Q1.5@2337.74,3282.89 Q1.6@2312.15,3282.89
NetD2_2: D2.2 R27.2
  other v2: 1894.35,3305
NetD6_4: D6.4 R78.2 | length 114.5
  F.CU w10: R78.2@2861.33,2145.96 D6.4@2975.8,2145.96
NetD6_5: D6.5 R79.2 | length 112.1
  F.CU w10: R79.2@2863.73,2067.22 D6.5@2975.8,2067.22
NetD6_6: D6.6 R80.2 | length 111.3
  F.CU w10: R80.2@2866.33,1984.08 2971.4,1984.08 D6.6@2975.8,1988.48
NetF1_1: F1.1 J12.2 | length 145.3
  F.CU w20: F1.1@1837,5396.66 1837,5267.71 J12.2@1848.54,5256.17
NetF2_1: F2.1 J13.1 | length 249.7
  F.CU w20: F2.1@5063.13,6612.12 5072.14,6621.14 J13.1@5072.14,6858.04
NetF3_1: F3.1 J1.2 | length 154.5
  F.CU w20: F3.1@1837,5556.17 1837,5705 J1.2@1841,5709
NetJ1_1: J1.1 J4.1 J4.2 R62.2 | length 5195.6
  F.CU w10: J4.2@4349.23,6875.29 J4.1@4549.23,6875.29 4549.23,6651.56 4574.19,6626.59 R62.2@4574.19,6572.5
  F.CU w20: J1.1@1841,5809 1841,6546 2131,6836 2131,7464 2149,7482 4335.73,7482 4549.23,7268.5 J4.1@4549.23,6875.29
NetJ2_1: J2.1 J2.2 J12.1 R40.2 | length 4172.2
  F.CU w10: J2.2@3289.21,6881.14 J2.1@3489.21,6881.14 3489.21,6538.01 R40.2@3499.35,6527.87
  F.CU w20: J12.1@1848.54,5156.17 1982.96,5290.59 1982.96,6521.96 2300,6839 2300,7126.28 2462.72,7289 3277.46,7289 3277.5,7289.04 3289.21,7277.32 J2.2@3289.21,6881.14
NetQ1_3: Q1.3 R76.2 R77.1 | length 150.1
  F.CU w10: R77.1@2343.56,3134.32 2343.56,3180.11 2363.33,3199.88 Q1.3@2363.33,3206.12 2424.47,3206.12 R76.2@2430.8,3212.45
NetR1_2: R1.2 R2.1 R35.2 TP3.1 U2.3 | length 407.8
  F.CU w10: U2.3@4157.66,3755.89 4172.64,3740.91 4357.49,3740.91 4367.33,3750.75 4426.25,3750.75 R1.2@4437,3761.5 ; TP3.1@4437,3701.97 R1.2@4437,3761.5 ; R35.2@4490.54,3763 4438.5,3763 R1.2@4437,3761.5
NetR7_2: R7.2 R10.1 U1.13 | length 179.2
  F.CU w10: U1.13@3401.33,3621.86 3420.04,3621.86 3426.85,3628.67 3426.85,3630.74 3432.7,3636.6 3455.79,3636.6 3458.03,3638.84 3470.92,3638.84 3478.01,3645.93 3478.01,3653.23 3491.02,3666.24 3498.32,3666.24 3506.77,3674.69 3506.77,3676.57 3514.92,3684.72 3516.99,3684.72 3525.14,3692.87 3525.14,3694.84 3531.02,3700.72 R10.1@3540.08,3700.72
NetR8_1: R8.1 R87.2 TP13.1 | length 362.7
  F.CU w10: R8.1@3541.83,3533.04 3588.16,3533.04 3616.65,3504.56 R87.2@3818.28,3504.56 3814.28,3508.55 3814.28,3555.72 TP13.1@3799,3571
NetR10_2: R10.2 R18.1 U1.14 | length 1351.2
  F.CU w10: v2(3397.1,2908.57) 3295.04,3010.63 3295.04,3574.92 3391.98,3671.86 U1.14@3401.33,3671.86 3401.33,3694.86 3407.19,3700.72 R10.2@3477.09,3700.72 ; v2(3469.93,2905.01) 3487.41,2905.01 3681.28,2711.14 R18.1@3681.28,2682.12
  B.CU w10: v2(3397.1,2908.57) 3398.88,2906.79 3468.15,2906.79 v2(3469.93,2905.01)
NetR11_1: R11.1 U3.7 | length 96.5
  F.CU w10: U3.7@4631.35,2916.67 4654.79,2916.67 R11.1@4706.42,2865.04
NetR12_1: R12.1 R13.2 | length 60.6
  F.CU w10: R13.2@1931.83,4661.43 1931.83,4605.34 R12.1@1935.04,4602.13
NetR12_2: R12.2 R14.1 | length 53.5
  F.CU w10: R14.1@1935.04,4469.87 R12.2@1935.04,4523.39
NetR13_1: R13.1 R16.1 | length 63.8
  F.CU w10: R13.1@1931.83,4740.17 1935.04,4743.37 R16.1@1935.04,4802.61
NetR24_1: R24.1 U3.3 | length 91.1
  F.CU w10: U3.3@4586.08,2851.71 4586.08,2814.16 4623.42,2776.82 R24.1@4623.42,2776.07
NetR25_2: R25.2 R30.1 U1.5 | length 133.7
  F.CU w10: R25.2@3119,3396.93 3119,3452.94 R30.1@3118.96,3452.98 3119.95,3452.98 3138.83,3471.86 U1.5@3188.74,3471.86
NetR26_1: R26.1 R28.2 U4.3 | length 119.8
  F.CU w10: U4.3@1767.36,2950.4 1767.36,2891.99 R28.2@1772.2,2887.15 1794.7,2887.15 1809.29,2872.56 R26.1@1809.29,2861.15
NetR32_1: R32.1 R34.2 U8.10 | length 245.2
  F.CU w10: U8.10@4666.33,4964.35 4667.23,4963.44 R34.2@4831.73,4963.44 ; R34.2@4831.73,4962.18 R34.2@4831.73,4963.44 ; R32.1@4833.07,5041.1 4831.73,5039.75 R34.2@4831.73,4963.44
NetR33_1: R33.1 U8.4 U8.9 | length 389.5
  F.CU w10: R33.1@4384.51,4952.34 4384.51,4955.03 4497.76,4955.03 4513.63,4970.91 4514.4,4970.91 4534.39,4990.89 v2(4583.25,4990.89) 4601.49,4990.89 U8.4@4602.94,4989.44 ; U8.9@4662,4939.25 4687.16,4939.25 v2(4688.39,4940.48)
  B.CU w10: v2(4583.25,4990.89) 4637.98,4990.89 v2(4688.39,4940.48)
NetR34_1: R34.1 R88.2 U8.5 | length 405.8
  F.CU w10: v2(4571.06,4949.01) 4572.92,4950.86 4572.92,4953.61 4581.76,4962.46 4591.21,4962.46 4593.1,4964.35 U8.5@4598.61,4964.35 ; v2(4779.7,4916.91) 4797.42,4899.19 R34.1@4831.73,4899.19 R88.2@4831.73,4810.22
  B.CU w10: v2(4571.06,4949.01) 4602.31,4917.76 4778.85,4917.76 v2(4779.7,4916.91)
NetR37_1: R37.1 R38.2 | length 76.2
  F.CU w10: R37.1@3196.74,6527.87 R38.2@3272.97,6527.87
NetR37_2: R37.2 R39.1 | length 60.8
  F.CU w10: R39.1@3057.21,6527.87 R37.2@3118,6527.87
NetR38_1: R38.1 R40.1 | length 68.9
  F.CU w10: R38.1@3351.72,6527.87 R40.1@3420.61,6527.87
NetR57_1: R57.1 R58.2 | length 74.3
  F.CU w10: R57.1@4275.57,6574.86 4277.94,6572.5 R58.2@4348.9,6572.5
NetR57_2: R57.2 R60.1 | length 63.8
  F.CU w10: R60.1@4132.99,6574.86 R57.2@4196.83,6574.86
NetR58_1: R58.1 R62.1 | length 67.8
  F.CU w10: R58.1@4427.64,6572.5 R62.1@4495.45,6572.5
NetR73_1: R73.1 U3.4 | length 118.6
  F.CU w10: U3.4@4605.76,2851.71 4605.76,2845.17 4606.04,2844.9 4612.57,2844.9 4668.23,2789.24 R73.1@4694.65,2789.24
NetR75_2: R75.2 U3.5 | length 162.4
  F.CU w10: U3.5@4631.35,2877.3 4631.35,2859.38 4669,2821.73 4714.54,2821.73 R75.2@4746.85,2789.42
NetR81_2: R81.2 R82.1 U6.3 | length 149.3
  F.CU w20: R82.1@3266.83,4897.93 3266.83,4818.23 3267.41,4817.66 U6.3@3336.22,4817.66
PA13_UART0-TX_XDS: J1/J3.29 J7.2 | length 199.5
  F.CU w10: J7.2@3764.28,2827.3 3766.58,2825 J1/J3.29@3962.78,2825
PA14_UART0-RX_XDS: J1/J3.30 J7.1 | length 199.5
  F.CU w10: J7.1@3764.28,2927.3 3960.48,2927.3 J1/J3.30@3962.78,2925
PB4: J2/J4.40 R79.1 | length 455.2
  F.CU w10: J2/J4.40@2363,2025 2758.52,2025 R79.1@2800.74,2067.22
PB5: J2/J4.39 R78.1 | length 444
  F.CU w10: J2/J4.39@2363,2125 2777.38,2125 R78.1@2798.34,2145.96
Primary: D7.2 D8.1 F1.2 F3.2 J8.1 J8.2 K1.4 Primary.1 R16.2 R27.1 R29.2 R71.1 | length 2390.9
  F.CU w10: R16.2@1930.64,4891.69 R16.2@1935.04,4887.29
  F.CU w20: D8.1@963.33,5271 1114.37,5271 1123.93,5280.55 ; 1116,4561 1116,3746 1150,3712 R29.2@1383.15,3712 ; 1696.72,4881.35 R16.2@1935.04,4881.35 ; R27.1@1801.42,3508.47 1921.53,3508.47 Primary.1@1972,3458
  B.CU w20: R29.2@1383.15,3712 1456,3712 1566.24,3601.76 1658.56,3601.76 1802.32,3458 Primary.1@1972,3458
  other v1: 1287.74,5121.73 1417.5,5121.73 1605.31,5121.68 1186.33,5284.78 1580.95,5400 1580.95,5489.78 1217,5573.1 1580.95,5575 1543,5845 1434,5914 1658.54,5926
RelayControl: C71.2 D8.2 J6.1 J6.2 K1.3 R72.2 | length 1444.9
  F.CU w20: R72.2@786.49,6179.09 786.49,6271.51 v2(788.97,6274) 1090.2,6274 ; v2(795,5355) 804.67,5345.33 D8.2@804.67,5271 ; J6.1@1698,6871 J6.1@1725,6898
  B.CU w20: v2(788.97,6274) 788.97,5361.03 v2(795,5355)
relayGPIO: J2/J4.33 R77.2 | length 427.4
  F.CU w10: J2/J4.33@2363,2725 2406.56,2768.56 R77.2@2406.56,3134.32
Rogo+: R84.1 | length 41
  F.CU w3.94: R84.1@4571.32,3808.53 4610.86,3819.33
